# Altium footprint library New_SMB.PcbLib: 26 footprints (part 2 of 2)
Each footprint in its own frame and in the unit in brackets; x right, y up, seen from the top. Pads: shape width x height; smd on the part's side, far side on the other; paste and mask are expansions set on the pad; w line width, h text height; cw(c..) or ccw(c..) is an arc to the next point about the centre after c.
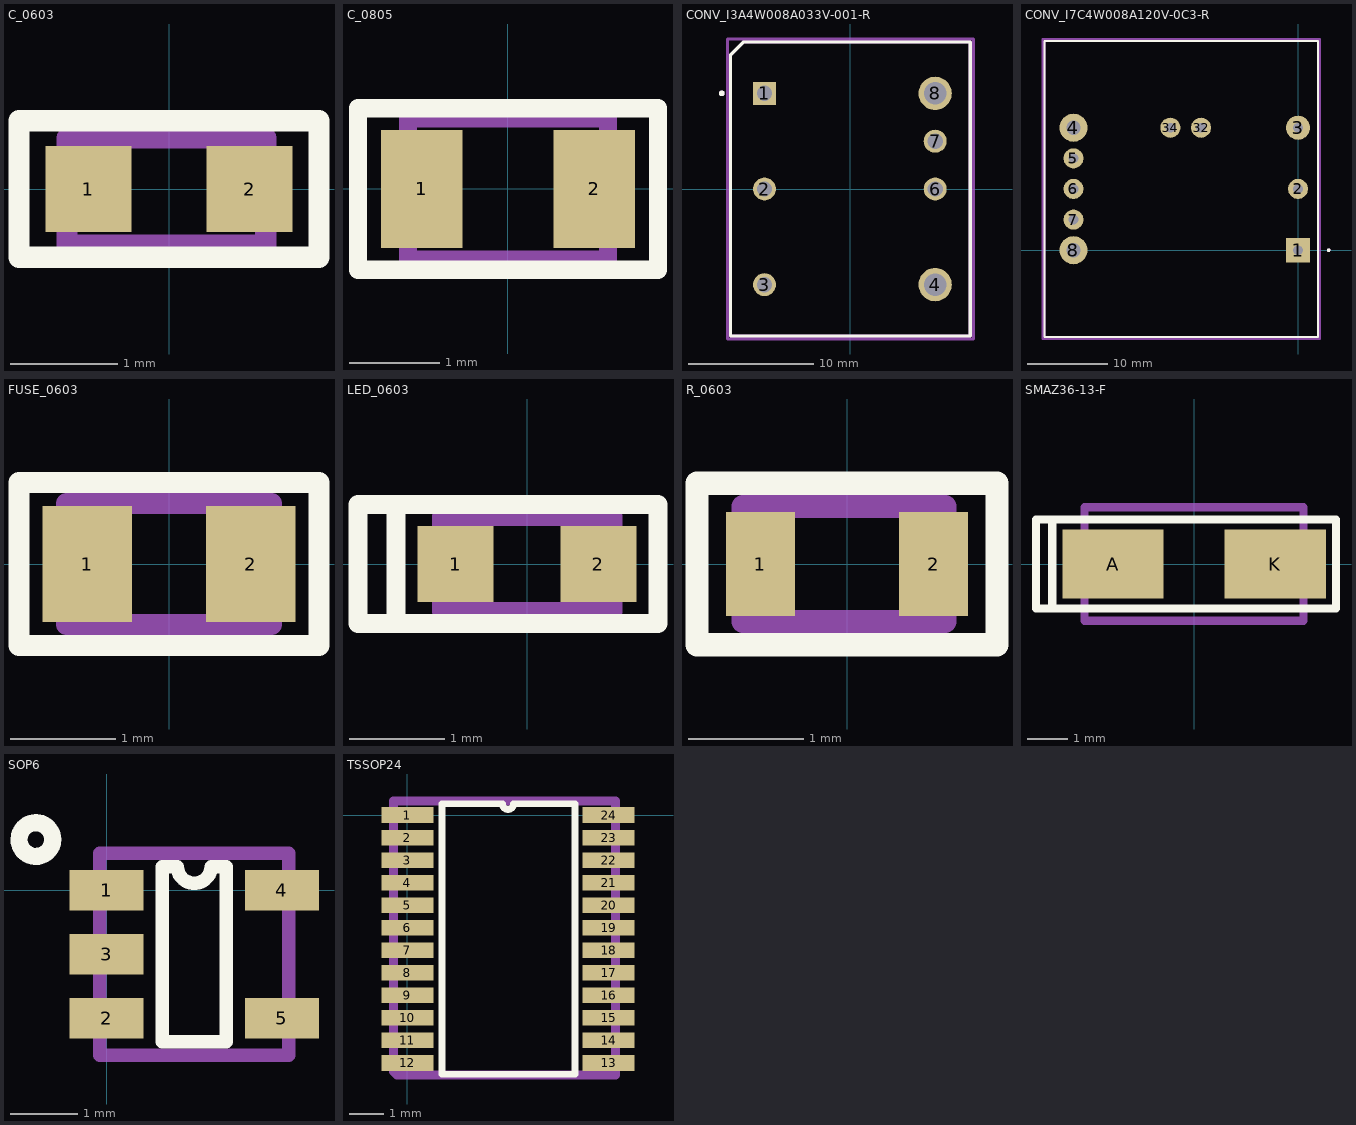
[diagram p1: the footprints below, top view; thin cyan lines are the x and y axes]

## C_0603 [mm]
pads (2):
  rect 0.8x0.8 smd: 1(-0.75,0) 2(0.75,0)
Top Overlay:
  lines w0.2: -1.397,-0.635 -1.397,0.635 1.397,0.635 1.397,-0.635 -1.397,-0.635
Mechanical 1:
  lines w0.2: -0.95,-0.525 0.9,-0.525 0.9,0.475 -0.95,0.475 -0.95,-0.525
  text ".Designator" at -0.765,-0.23 h0.15
3D body "CAP_CL10B_SAM.step": height 0.89, standoff 0, extent -0.851,-0.444 0.851,0.444

## C_0805 [mm]
pads (2):
  rect 0.9x1.3 smd: 1(-0.95,0) 2(0.95,0)
Top Overlay:
  lines w0.2: -1.651,-0.889 -1.651,0.889 1.651,0.889 1.651,-0.889 -1.651,-0.889
Mechanical 1:
  lines w0.2: -1.1,-0.775 -1.1,0.775 1.1,0.775 1.1,-0.775 -1.1,-0.775
  text ".Designator" at -0.96,0.378 h0.19
3D body "CAP_CL21_SAM.step": height 1.22, standoff -0.03, extent -1,-0.675 1,0.675

## CONV_I3A4W008A033V-001-R [mm]
pads (7):
  rect 1.83x1.83 hole 1.22: 1(-6.85,7.62)
  round 1.83 hole 1.22: 2(-6.85,0) 3(-6.85,-7.62) 6(6.75,0) 7(6.75,3.81)
  round 2.655 hole 1.77: 4(6.75,-7.62) 8(6.75,7.62)
Top Overlay:
  circle w0.254: c-10.25,7.62 r0.1
  lines w0.254: -9.55,-11.7 9.55,-11.7 9.55,11.7 -8.55,11.7 -9.55,10.7 -9.55,-11.7
Mechanical 10:
  circle w0.254: c-10.25,7.62 r0.1
  lines w0.254: -9.55,-11.7 -9.55,10.7 -8.55,11.7 9.55,11.7 9.55,-11.7 -9.55,-11.7
Mechanical 12:
  lines w0.254: -9.8,-11.95 9.8,-11.95 9.8,11.95 -9.8,11.95 -9.8,-11.95
3D body "I3A4W008A033V-001-R.step": height 9.76, standoff -3.47, extent -9.511,-11.724 9.539,11.645

## CONV_I7C4W008A120V-0C3-R [mm]
pads (10):
  rect 3x3 hole 1.22 paste-2539.97 mask+0: 1(0,0)
  round 2.5 hole 1.22 paste-2539.97 mask+0: 2(0,7.62) 5(-27.94,11.43) 6(-27.94,7.62) 7(-27.94,3.81) 32(-12.07,15.24) 34(-15.88,15.24)
  round 3 hole 1.22 paste-2539.97 mask+0: 3(0,15.24)
  round 3.5 hole 1.77 paste-2539.97 mask+0: 4(-27.94,15.24) 8(-27.94,0)
Top Overlay:
  circle w0.254: c3.81,0 r0.1
  lines w0.254: -31.54,-10.8 2.5,-10.8 2.5,26.03 -31.54,26.03 -31.54,-10.8
Mechanical 11:
  circle w0.254: c3.81,0 r0.1
  lines w0.254: -31.54,-10.8 2.5,-10.8 2.5,26.03 -31.54,26.03 -31.54,-10.8
Mechanical 13:
  lines w0.254: -31.79,-11.05 2.75,-11.05 2.75,26.28 -31.79,26.28 -31.79,-11.05
3D body "I7C4W008A120V-0C3-R.step": height 13.46, standoff -4.57, extent -31.496,-10.795 2.54,26.035

## FUSE_0603 [mm]
pads (2):
  rect 0.85x1.1 smd: 1(-0.775,0) 2(0.775,0)
Top Overlay:
  lines w0.2: -1.425,-0.775 1.425,-0.775 1.425,0.775 -1.425,0.775 -1.425,-0.775
Mechanical 1:
  lines w0.2: -0.975,-0.575 0.975,-0.575 0.975,0.575 -0.975,0.575 -0.975,-0.575
  text ".Designator" at -0.76,0.187 h0.14
3D body "0603_AVX.step": height 0.89, standoff 0, extent -0.876,-0.483 0.876,0.483

## LED_0603 [mm]
pads (2):
  rect 0.8x0.8 smd: 1(-0.75,0) 2(0.75,0)
Top Overlay:
  lines w0.2: -1.45,-0.625 1.375,-0.625 1.375,0.625 -1.45,0.625 ; -1.775,-0.625 -1.775,0.625 -1.375,0.625 -1.375,-0.625 -1.775,-0.625
Mechanical 1:
  lines w0.2: -0.9,-0.5 -0.9,0.5 0.9,0.5 0.9,-0.5 -0.9,-0.5
  text ".Designator" at -0.76,0.19 h0.15
3D body "LED_B1931NG_HVK.step": height 0.41, standoff 0, extent -0.8,-0.406 0.8,0.406

## R_0603 [mm]
pads (2):
  rect 0.6x0.9 smd: 1(-0.75,0) 2(0.75,0)
Top Overlay:
  lines w0.2: -1.3,-0.7 1.3,-0.7 1.3,0.7 -1.3,0.7 -1.3,-0.7
Mechanical 1:
  lines w0.2: -0.9,-0.5 0.85,-0.5 0.85,0.5 -0.9,0.5 -0.9,-0.5
  text ".Designator" at -0.735,0.187 h0.14
3D body "RMCF0603_stp.stp": height 0.44, standoff -0.01, extent -0.8,-0.4 0.75,0.4

## SMAZ36-13-F [mm]
pads (2):
  rect 2.5x1.7 smd: A(-2,0) K(2,0)
Top Overlay:
  lines w0.2: -3.5,-1.1 -3.9,-1.1 -3.9,1.1 -3.5,1.1 ; -3.5,-1.1 -3.5,1.1 ; -3.5,-1.1 3.5,-1.1 3.5,1.1 -3.5,1.1
Mechanical 1:
  lines w0.2: -2.7,-1.4 -2.7,1.4 2.7,1.4 2.7,-1.4 -2.7,-1.4
  text ".Designator" at -2.375,0.708 h0.4
3D body "SMAZ36-13-F.step": height 2.4, standoff 0, extent -2.598,-1.302 2.598,1.302

## SOP6 [mm]
pads (5):
  rect 1.1x0.6 smd: 1(0,0) 2(0,-1.9) 3(0,-0.95) 4(2.6,0) 5(2.6,-1.9)
Top Overlay:
  lines w0.2: 0.825,-2.25 0.825,0.35 1.05,0.35 ccw(c1.3,0.35) 1.55,0.35 1.775,0.35 1.775,-2.25 0.825,-2.25
  lines w0.254: -0.8,0.734 cw(c-1.05,0.75) -0.8,0.75
Mechanical 1:
  lines w0.2: -0.1,-2.45 2.7,-2.45 2.7,0.55 -0.1,0.55 -0.1,-2.45
  text ".Designator" at 1.382,-2.19 h0.25
3D body "TLV73312PDBVR.step": height 1.45, standoff 0, extent -0.1,-2.4 2.7,0.5

## TSSOP24 [mm]
pads (24):
  rect 1.5x0.45 smd mask+0.05: 1(0,0) 2(0,-0.65) 3(0,-1.3) 4(0,-1.95) 5(0,-2.6) 6(0,-3.25) 7(0,-3.9) 8(0,-4.55) 9(0,-5.2) 10(0,-5.85) 11(0,-6.5) 12(0,-7.15) 13(5.8,-7.15) 14(5.8,-6.5) 15(5.8,-5.85) 16(5.8,-5.2) 17(5.8,-4.55) 18(5.8,-3.9) 19(5.8,-3.25) 20(5.8,-2.6) 21(5.8,-1.95) 22(5.8,-1.3) 23(5.8,-0.65) 24(5.8,0)
Top Overlay:
  lines w0.2: 1,-7.475 1,0.325 2.738,0.325 ccw(c2.9,0.325) 3.062,0.325 4.828,0.325 4.828,-7.475 1,-7.475
  text "." at -1.504,-0.108 h1.52
Mechanical 1:
  lines w0.254: -0.4,-7.4 -0.4,0.4 6,0.4 6,-7.5 -0.3,-7.5 -0.4,-7.4
  text ".Designator" at -0.18,-7.18 h0.6
3D body "TCA6416APWR.step": height 1.2, standoff 0, extent -0.327,-7.464 6.073,0.336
